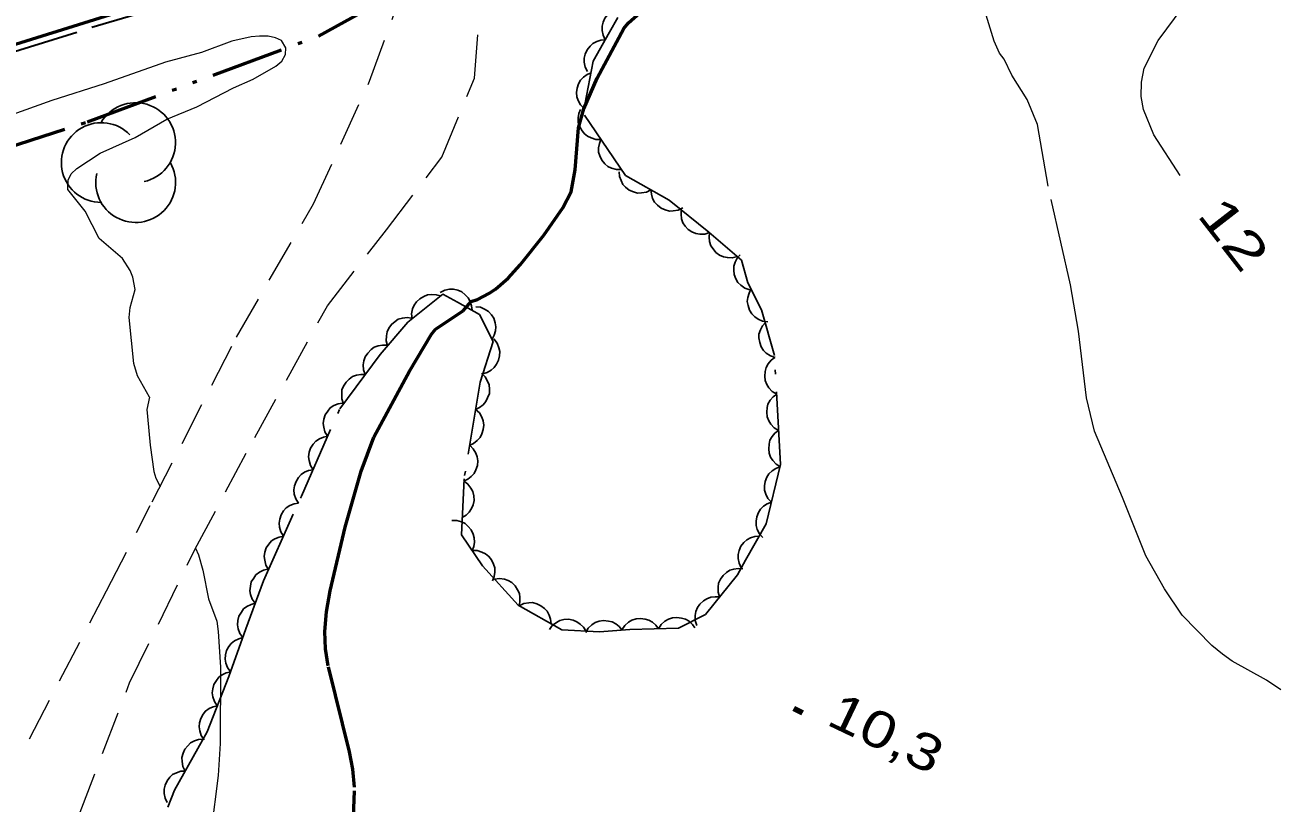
# Model space of a CAD drawing. Extents: x 355726 to 357533, y 5103782 to 5105258.
# Drawn here: x 356018.2 to 356069.6, y 5104734.5 to 5104766.6 of the extents above; entities that cross this region are included whole.
import ezdxf
from ezdxf.enums import TextEntityAlignment as Align

# ---------------------------------------------------------------- set-up
doc = ezdxf.new("R2010")
doc.units = 0
doc.header["$LTSCALE"] = 0.6
for name, pattern in [('DASH_DOUBLE_DOT', [9.2, 5, -1.2, 0.3, -1.2, 0.3, -1.2]), ('DOT_DASHED', [7.7, 5, -1.2, 0.3, -1.2]), ('LONG_DASHED', [7.5, 6, -1.5]), ('MEDIUM_DASHED', [4.5, 3, -1.5])]:
    doc.linetypes.add(name, pattern=pattern)
for name, color, linetype, lineweight in [('1', 7, 'LONG_DASHED', 53), ('19', 7, 'Continuous', 13), ('2', 7, 'LONG_DASHED', 13), ('21', 7, 'LONG_DASHED', 35), ('3', 7, 'Continuous', 140), ('4', 7, 'DASH_DOUBLE_DOT', 53), ('44', 7, 'Continuous', 25)]:
    doc.layers.add(name, color=color, linetype=linetype, lineweight=lineweight)

msp = doc.modelspace()

# ---------------------------------------------------------------- linework, layer by layer
at = {"layer": '1', "linetype": 'Continuous'}
msp.add_lwpolyline([(356036.57, 5104755.18), (356036.83, 5104755.26), (356037.3, 5104755.51), (356037.57, 5104755.69), (356038.09, 5104756.15), (356038.59, 5104756.69), (356039.56, 5104757.91), (356040.34, 5104759.04), (356040.69, 5104759.7), (356040.85, 5104760.61), (356040.99, 5104762.34), (356041.21, 5104763.12), (356041.76, 5104764.38), (356042.86, 5104766.43), (356043.05, 5104766.67), (356044.33, 5104767.8), (356044.89, 5104768.42), (356045.2, 5104768.69), (356046.34, 5104769.49), (356047.27, 5104769.98), (356048.57, 5104770.51), (356050.95, 5104771.79), (356053.92, 5104773.05)], dxfattribs=at)
at = {"layer": '1'}
for points in [[(356030.77, 5104743.26), (356031.38, 5104745.88), (356032.04, 5104748.19), (356032.57, 5104749.59), (356034.03, 5104752.32), (356034.94, 5104753.84), (356035.1, 5104754.04), (356036.24, 5104754.8), (356036.57, 5104755.18)], [(356043.49, 5104709.57), (356042.09, 5104710.94), (356037.19, 5104715.19), (356036.61, 5104715.88), (356034.23, 5104719.58), (356032.63, 5104722.18), (356031.96, 5104723.38), (356031.72, 5104724.01), (356031.58, 5104724.66), (356031.55, 5104725.34), (356031.71, 5104729.23), (356031.63, 5104731.43), (356031.77, 5104735.18), (356031.7, 5104735.91), (356031.56, 5104736.63), (356030.69, 5104740.17), (356030.57, 5104740.87), (356030.55, 5104741.59), (356030.61, 5104742.4), (356030.77, 5104743.26)]]:
    msp.add_lwpolyline(points, dxfattribs=at)
at = {"layer": '19', "linetype": 'MEDIUM_DASHED'}
for points in [[(356023.44, 5104746.93), (356026.91, 5104753.72), (356030.08, 5104759.21), (356032.39, 5104764.26), (356033.38, 5104766.97), (356033.05, 5104768.45), (356032.86, 5104769.13), (356032.09, 5104769.82)], [(355997.8, 5104670.73), (355999.08, 5104674.22), (356000.32, 5104676.94), (356001.43, 5104679.09), (356002.21, 5104680.3), (356006.1, 5104687.7), (356008.11, 5104691.5), (356009.62, 5104696.76), (356011.14, 5104701.84), (356012.62, 5104707.21), (356014.22, 5104712.09), (356015.74, 5104717.23), (356017.57, 5104723.26), (356018.4, 5104728.58), (356020.43, 5104734.04), (356022.51, 5104739.47), (356025.19, 5104744.96), (356027.66, 5104749.58), (356030.65, 5104755.01), (356033.08, 5104758.13), (356035.37, 5104761.13), (356036.71, 5104764.38), (356036.94, 5104767.51)], [(356018.38, 5104737.16), (356021.56, 5104743.26), (356023.36, 5104746.78)]]:
    msp.add_lwpolyline(points, dxfattribs=at)
at = {"layer": '2'}
for points in [[(356069.9, 5104739.18), (356069.32, 5104739.58), (356067.9, 5104740.36), (356067.5, 5104740.65), (356067.06, 5104741.01), (356065.84, 5104742.26), (356065.12, 5104743.34), (356064.35, 5104744.7), (356063.39, 5104747.11), (356062.23, 5104749.84), (356061.91, 5104751.21), (356061.58, 5104753.96), (356061.24, 5104755.87), (356060.32, 5104759.93), (356059.89, 5104762.48), (356059.46, 5104763.51), (356058.83, 5104764.51), (356058.52, 5104765.17), (356058.32, 5104765.41), (356058.1, 5104765.91), (356057.55, 5104767.73)], [(356065.76, 5104760.37), (356064.68, 5104762.05), (356064.25, 5104763.09), (356064.16, 5104763.63), (356064.17, 5104764.22), (356064.28, 5104764.79), (356064.85, 5104765.93), (356065.89, 5104767.32)], [(356023.33, 5104751.24), (356023.22, 5104750.74), (356023.24, 5104750.44), (356023.36, 5104749.26), (356023.51, 5104748.18), (356023.59, 5104747.9), (356023.76, 5104747.56)], [(356025.22, 5104745.02), (356025.35, 5104744.75), (356025.53, 5104744.11), (356025.75, 5104742.94), (356026.1, 5104742.01), (356026.16, 5104741.59), (356026.25, 5104740.12), (356026.24, 5104736.97), (356026.16, 5104735.66), (356025.8, 5104732.91)]]:
    msp.add_lwpolyline(points, dxfattribs=at)
at = {"layer": '2', "linetype": 'Continuous'}
msp.add_lwpolyline([(356023.33, 5104751.24), (356022.83, 5104752.12), (356022.68, 5104752.63), (356022.49, 5104754.53), (356022.53, 5104754.94), (356022.74, 5104755.68), (356022.64, 5104756.18), (356022.53, 5104756.46), (356022.22, 5104756.95), (356021.26, 5104757.78), (356020.68, 5104758.9), (356019.96, 5104759.8), (356019.98, 5104760.18), (356020.1, 5104760.44), (356020.33, 5104760.66), (356021.29, 5104761.3), (356022.74, 5104761.94), (356024.04, 5104762.69), (356025.28, 5104763.21), (356026.78, 5104763.98), (356027.6, 5104764.34), (356028.53, 5104764.88), (356028.77, 5104765.09), (356028.92, 5104765.36), (356028.94, 5104765.63), (356028.76, 5104765.93), (356028.51, 5104766.05), (356028.21, 5104766.12), (356027.86, 5104766.12), (356027.51, 5104766.09), (356026.72, 5104765.91), (356025.47, 5104765.44), (356023.98, 5104765.04), (356021.46, 5104764.15), (356019.3, 5104763.47), (356016.23, 5104762.36)], dxfattribs=at)
at = {"layer": '21', "linetype": 'Continuous', "lineweight": 53}
msp.add_lwpolyline([(356031.16, 5104769.57), (356022.16, 5104767.13), (356004.71, 5104761.68), (355990.39, 5104758.11), (355976.24, 5104753.88), (355961.38, 5104749.66)], dxfattribs=at)
at = {"layer": '21'}
msp.add_lwpolyline([(356002.9, 5104759.34), (356004.54, 5104760.73), (356007.99, 5104762.24), (356012.6, 5104763.88), (356020.96, 5104766.48), (356032.1, 5104769.8)], dxfattribs=at)
at = {"layer": '3'}
msp.add_line((356049.85, 5104738.41), (356050.21, 5104738.24), dxfattribs=at)
at = {"layer": '4'}
msp.add_lwpolyline([(355997.31, 5104755.28), (356004.08, 5104756.23), (356006.82, 5104757.38), (356011.73, 5104759.66), (356020.78, 5104762.59), (356030.28, 5104766.12), (356032.42, 5104767.29)], dxfattribs=at)
at = {"layer": '44', "linetype": 'DOT_DASHED'}
for points in [[(356044.72, 5104759.36), (356042.92, 5104760.38), (356041.18, 5104762.94), (356041.6, 5104765.08), (356042.27, 5104766.28), (356042.61, 5104766.88)], [(356022.38, 5104730.06), (356024.35, 5104735.05), (356025.7, 5104737.45), (356026.59, 5104739.73), (356027.3, 5104741.7), (356028.02, 5104743.68), (356029.58, 5104747.16), (356031.16, 5104750.76), (356032.82, 5104753), (356033.96, 5104754.33), (356035.41, 5104755.49), (356036.01, 5104755.16), (356036.92, 5104754.65), (356037.48, 5104753.54), (356036.94, 5104751.86), (356036.28, 5104747.88), (356036.17, 5104745.57), (356037.04, 5104744.29), (356038.5, 5104742.67), (356040.31, 5104741.65), (356041.85, 5104741.58), (356043.1, 5104741.67), (356045.11, 5104741.72), (356046.22, 5104742.29), (356047.54, 5104743.92), (356047.87, 5104744.52), (356048.72, 5104746.03), (356049.3, 5104748.47), (356049.06, 5104752.96), (356048.53, 5104754.84), (356047.96, 5104755.95), (356047.7, 5104756.89), (356046.36, 5104758.04), (356044.72, 5104759.36)]]:
    msp.add_lwpolyline(points, dxfattribs=at)
at = {"layer": '44'}
for points in [[(356042.09, 5104765.97), (356042, 5104766.15), (356041.97, 5104766.35), (356041.96, 5104766.52), (356042.01, 5104766.69), (356042.08, 5104766.86), (356042.2, 5104767.01), (356042.32, 5104767.12), (356042.48, 5104767.2), (356042.65, 5104767.26), (356042.83, 5104767.27)], [(356041.36, 5104764.66), (356041.27, 5104764.84), (356041.23, 5104765.04), (356041.23, 5104765.21), (356041.27, 5104765.38), (356041.35, 5104765.55), (356041.47, 5104765.7), (356041.58, 5104765.81), (356041.74, 5104765.89), (356041.91, 5104765.95), (356042.09, 5104765.96)], [(356041.22, 5104763.13), (356041.07, 5104763.28), (356040.97, 5104763.46), (356040.92, 5104763.61), (356040.91, 5104763.79), (356040.93, 5104763.97), (356040.99, 5104764.15), (356041.07, 5104764.3), (356041.19, 5104764.42), (356041.34, 5104764.53), (356041.51, 5104764.6)], [(356041.91, 5104761.86), (356041.71, 5104761.86), (356041.51, 5104761.92), (356041.36, 5104761.99), (356041.23, 5104762.1), (356041.11, 5104762.25), (356041.03, 5104762.42), (356040.98, 5104762.57), (356040.98, 5104762.75), (356041, 5104762.93), (356041.07, 5104763.1)], [(356042.76, 5104760.62), (356042.55, 5104760.62), (356042.35, 5104760.68), (356042.2, 5104760.75), (356042.07, 5104760.86), (356041.95, 5104761), (356041.87, 5104761.18), (356041.82, 5104761.33), (356041.82, 5104761.51), (356041.85, 5104761.69), (356041.91, 5104761.86)], [(356043.97, 5104759.78), (356043.79, 5104759.69), (356043.59, 5104759.66), (356043.42, 5104759.65), (356043.25, 5104759.7), (356043.08, 5104759.77), (356042.93, 5104759.89), (356042.82, 5104760.01), (356042.74, 5104760.17), (356042.68, 5104760.34), (356042.67, 5104760.52)], [(356045.28, 5104759.04), (356045.09, 5104758.95), (356044.89, 5104758.92), (356044.73, 5104758.91), (356044.56, 5104758.96), (356044.39, 5104759.03), (356044.24, 5104759.15), (356044.12, 5104759.27), (356044.04, 5104759.43), (356043.99, 5104759.6), (356043.97, 5104759.78)], [(356046.39, 5104758.02), (356046.19, 5104757.96), (356045.99, 5104757.96), (356045.82, 5104757.98), (356045.66, 5104758.05), (356045.51, 5104758.15), (356045.38, 5104758.29), (356045.29, 5104758.43), (356045.23, 5104758.59), (356045.21, 5104758.78), (356045.22, 5104758.96)], [(356047.53, 5104757.04), (356047.32, 5104756.98), (356047.12, 5104756.99), (356046.96, 5104757.02), (356046.8, 5104757.09), (356046.65, 5104757.2), (356046.53, 5104757.35), (356046.44, 5104757.48), (356046.39, 5104757.65), (356046.37, 5104757.84), (356046.39, 5104758.02)], [(356048.04, 5104755.67), (356047.84, 5104755.73), (356047.68, 5104755.85), (356047.55, 5104755.96), (356047.47, 5104756.12), (356047.4, 5104756.29), (356047.38, 5104756.48), (356047.38, 5104756.64), (356047.44, 5104756.81), (356047.52, 5104756.97), (356047.64, 5104757.11)], [(356035.29, 5104755.55), (356035.48, 5104755.65), (356035.68, 5104755.69), (356035.84, 5104755.69), (356036.02, 5104755.65), (356036.18, 5104755.58), (356036.33, 5104755.46), (356036.45, 5104755.34), (356036.53, 5104755.19), (356036.59, 5104755.01), (356036.61, 5104754.83)], [(356048.78, 5104754.35), (356048.57, 5104754.38), (356048.39, 5104754.46), (356048.25, 5104754.55), (356048.13, 5104754.68), (356048.03, 5104754.83), (356047.97, 5104755.02), (356047.94, 5104755.18), (356047.96, 5104755.35), (356048.01, 5104755.53), (356048.09, 5104755.69)], [(356034.14, 5104754.47), (356034.12, 5104754.68), (356034.16, 5104754.88), (356034.22, 5104755.03), (356034.32, 5104755.17), (356034.46, 5104755.3), (356034.62, 5104755.39), (356034.77, 5104755.46), (356034.95, 5104755.47), (356035.13, 5104755.46), (356035.31, 5104755.41)], [(356036.76, 5104754.97), (356036.96, 5104754.95), (356037.15, 5104754.86), (356037.29, 5104754.77), (356037.41, 5104754.64), (356037.5, 5104754.49), (356037.56, 5104754.3), (356037.59, 5104754.14), (356037.57, 5104753.97), (356037.52, 5104753.79), (356037.43, 5104753.63)], [(356033.13, 5104753.36), (356033.07, 5104753.56), (356033.08, 5104753.77), (356033.11, 5104753.93), (356033.18, 5104754.09), (356033.29, 5104754.24), (356033.44, 5104754.36), (356033.57, 5104754.45), (356033.74, 5104754.5), (356033.93, 5104754.52), (356034.11, 5104754.5)], [(356049.09, 5104752.87), (356048.89, 5104752.94), (356048.72, 5104753.05), (356048.6, 5104753.16), (356048.51, 5104753.32), (356048.45, 5104753.49), (356048.42, 5104753.68), (356048.42, 5104753.84), (356048.48, 5104754.01), (356048.56, 5104754.18), (356048.68, 5104754.31)], [(356037.51, 5104753.64), (356037.64, 5104753.47), (356037.71, 5104753.28), (356037.75, 5104753.12), (356037.74, 5104752.95), (356037.7, 5104752.77), (356037.61, 5104752.6), (356037.52, 5104752.46), (356037.39, 5104752.35), (356037.23, 5104752.26), (356037.05, 5104752.21)], [(356032.21, 5104752.18), (356032.14, 5104752.37), (356032.13, 5104752.58), (356032.15, 5104752.74), (356032.21, 5104752.91), (356032.31, 5104753.06), (356032.45, 5104753.2), (356032.58, 5104753.3), (356032.74, 5104753.36), (356032.92, 5104753.39), (356033.1, 5104753.38)], [(356049.15, 5104751.37), (356048.97, 5104751.48), (356048.83, 5104751.63), (356048.74, 5104751.76), (356048.68, 5104751.93), (356048.66, 5104752.11), (356048.68, 5104752.3), (356048.71, 5104752.46), (356048.8, 5104752.61), (356048.92, 5104752.76), (356049.07, 5104752.87)], [(356031.32, 5104750.97), (356031.25, 5104751.17), (356031.24, 5104751.37), (356031.25, 5104751.54), (356031.32, 5104751.7), (356031.42, 5104751.86), (356031.55, 5104751.99), (356031.68, 5104752.09), (356031.85, 5104752.15), (356032.03, 5104752.18), (356032.21, 5104752.18)], [(356037, 5104752.22), (356037.15, 5104752.08), (356037.25, 5104751.9), (356037.31, 5104751.75), (356037.33, 5104751.57), (356037.32, 5104751.39), (356037.25, 5104751.21), (356037.18, 5104751.06), (356037.06, 5104750.93), (356036.92, 5104750.82), (356036.75, 5104750.74)], [(356049.23, 5104749.87), (356049.05, 5104749.98), (356048.91, 5104750.13), (356048.82, 5104750.27), (356048.76, 5104750.43), (356048.74, 5104750.62), (356048.76, 5104750.81), (356048.79, 5104750.96), (356048.88, 5104751.12), (356049, 5104751.26), (356049.15, 5104751.37)], [(356030.66, 5104749.63), (356030.55, 5104749.81), (356030.5, 5104750), (356030.48, 5104750.16), (356030.5, 5104750.34), (356030.56, 5104750.51), (356030.67, 5104750.67), (356030.77, 5104750.8), (356030.92, 5104750.9), (356031.09, 5104750.97), (356031.27, 5104751)], [(356036.75, 5104750.74), (356036.91, 5104750.6), (356037.01, 5104750.42), (356037.07, 5104750.27), (356037.09, 5104750.09), (356037.07, 5104749.91), (356037.01, 5104749.73), (356036.94, 5104749.58), (356036.82, 5104749.45), (356036.67, 5104749.34), (356036.51, 5104749.26)], [(356049.31, 5104748.37), (356049.13, 5104748.48), (356048.99, 5104748.63), (356048.9, 5104748.77), (356048.84, 5104748.93), (356048.82, 5104749.12), (356048.84, 5104749.31), (356048.87, 5104749.47), (356048.96, 5104749.62), (356049.08, 5104749.76), (356049.23, 5104749.87)], [(356030.06, 5104748.25), (356029.95, 5104748.43), (356029.9, 5104748.63), (356029.87, 5104748.79), (356029.9, 5104748.97), (356029.96, 5104749.14), (356030.06, 5104749.3), (356030.17, 5104749.43), (356030.32, 5104749.52), (356030.49, 5104749.6), (356030.66, 5104749.63)], [(356036.51, 5104749.26), (356036.66, 5104749.12), (356036.76, 5104748.94), (356036.82, 5104748.79), (356036.84, 5104748.62), (356036.83, 5104748.43), (356036.76, 5104748.25), (356036.69, 5104748.1), (356036.57, 5104747.97), (356036.43, 5104747.86), (356036.26, 5104747.78)], [(356048.93, 5104746.92), (356048.79, 5104747.07), (356048.7, 5104747.25), (356048.65, 5104747.41), (356048.65, 5104747.59), (356048.67, 5104747.77), (356048.75, 5104747.94), (356048.83, 5104748.09), (356048.96, 5104748.21), (356049.11, 5104748.31), (356049.28, 5104748.37)], [(356029.46, 5104746.88), (356029.35, 5104747.06), (356029.29, 5104747.25), (356029.27, 5104747.42), (356029.3, 5104747.59), (356029.36, 5104747.77), (356029.46, 5104747.93), (356029.57, 5104748.05), (356029.71, 5104748.15), (356029.88, 5104748.22), (356030.06, 5104748.25)], [(356036.28, 5104747.78), (356036.44, 5104747.66), (356036.56, 5104747.49), (356036.64, 5104747.35), (356036.68, 5104747.18), (356036.69, 5104746.99), (356036.65, 5104746.81), (356036.59, 5104746.65), (356036.49, 5104746.51), (356036.36, 5104746.38), (356036.2, 5104746.28)], [(356028.84, 5104745.51), (356028.73, 5104745.69), (356028.68, 5104745.89), (356028.66, 5104746.05), (356028.69, 5104746.22), (356028.75, 5104746.4), (356028.85, 5104746.56), (356028.96, 5104746.68), (356029.11, 5104746.78), (356029.28, 5104746.85), (356029.46, 5104746.88)], [(356048.58, 5104745.46), (356048.44, 5104745.61), (356048.35, 5104745.79), (356048.3, 5104745.95), (356048.3, 5104746.13), (356048.33, 5104746.31), (356048.4, 5104746.49), (356048.48, 5104746.63), (356048.61, 5104746.75), (356048.76, 5104746.85), (356048.93, 5104746.92)], [(356035.77, 5104746.16), (356035.98, 5104746.16), (356036.17, 5104746.1), (356036.32, 5104746.04), (356036.45, 5104745.92), (356036.57, 5104745.78), (356036.65, 5104745.6), (356036.7, 5104745.45), (356036.71, 5104745.27), (356036.68, 5104745.09), (356036.61, 5104744.92)], [(356028.23, 5104744.14), (356028.12, 5104744.32), (356028.07, 5104744.52), (356028.05, 5104744.68), (356028.07, 5104744.86), (356028.13, 5104745.03), (356028.24, 5104745.19), (356028.35, 5104745.32), (356028.49, 5104745.41), (356028.66, 5104745.48), (356028.84, 5104745.51)], [(356047.69, 5104744.21), (356047.6, 5104744.4), (356047.57, 5104744.6), (356047.56, 5104744.76), (356047.61, 5104744.93), (356047.68, 5104745.1), (356047.8, 5104745.25), (356047.92, 5104745.36), (356048.07, 5104745.44), (356048.25, 5104745.5), (356048.43, 5104745.52)], [(356036.61, 5104744.92), (356036.82, 5104744.92), (356037.01, 5104744.86), (356037.16, 5104744.79), (356037.3, 5104744.68), (356037.41, 5104744.54), (356037.49, 5104744.36), (356037.55, 5104744.21), (356037.55, 5104744.03), (356037.52, 5104743.85), (356037.45, 5104743.68)], [(356046.8, 5104743.01), (356046.74, 5104743.21), (356046.74, 5104743.41), (356046.76, 5104743.58), (356046.84, 5104743.74), (356046.94, 5104743.89), (356047.08, 5104744.02), (356047.22, 5104744.11), (356047.38, 5104744.16), (356047.57, 5104744.19), (356047.75, 5104744.17)], [(356027.68, 5104742.75), (356027.56, 5104742.92), (356027.49, 5104743.11), (356027.46, 5104743.27), (356027.48, 5104743.45), (356027.52, 5104743.63), (356027.62, 5104743.79), (356027.71, 5104743.92), (356027.85, 5104744.03), (356028.02, 5104744.11), (356028.19, 5104744.16)], [(356037.53, 5104743.74), (356037.74, 5104743.77), (356037.94, 5104743.74), (356038.1, 5104743.69), (356038.25, 5104743.6), (356038.38, 5104743.47), (356038.48, 5104743.31), (356038.56, 5104743.16), (356038.58, 5104742.99), (356038.58, 5104742.8), (356038.54, 5104742.63)], [(356027.17, 5104741.34), (356027.05, 5104741.51), (356026.98, 5104741.7), (356026.95, 5104741.86), (356026.96, 5104742.04), (356027.01, 5104742.22), (356027.11, 5104742.38), (356027.2, 5104742.52), (356027.34, 5104742.62), (356027.51, 5104742.7), (356027.68, 5104742.75)], [(356038.55, 5104742.64), (356038.74, 5104742.74), (356038.94, 5104742.77), (356039.1, 5104742.78), (356039.27, 5104742.73), (356039.44, 5104742.65), (356039.59, 5104742.53), (356039.7, 5104742.42), (356039.78, 5104742.26), (356039.84, 5104742.09), (356039.86, 5104741.91)], [(356045.86, 5104741.84), (356045.8, 5104742.04), (356045.8, 5104742.25), (356045.82, 5104742.41), (356045.89, 5104742.57), (356045.99, 5104742.72), (356046.14, 5104742.85), (356046.27, 5104742.94), (356046.44, 5104743), (356046.62, 5104743.02), (356046.8, 5104743.01)], [(356042.78, 5104741.66), (356042.9, 5104741.84), (356043.05, 5104741.97), (356043.19, 5104742.06), (356043.36, 5104742.11), (356043.54, 5104742.13), (356043.73, 5104742.1), (356043.89, 5104742.06), (356044.04, 5104741.97), (356044.18, 5104741.85), (356044.28, 5104741.7)], [(356044.28, 5104741.7), (356044.4, 5104741.88), (356044.55, 5104742.01), (356044.69, 5104742.1), (356044.86, 5104742.15), (356045.04, 5104742.17), (356045.23, 5104742.14), (356045.39, 5104742.1), (356045.54, 5104742.01), (356045.68, 5104741.88), (356045.78, 5104741.74)], [(356039.79, 5104741.67), (356039.91, 5104741.84), (356040.08, 5104741.96), (356040.22, 5104742.04), (356040.39, 5104742.08), (356040.58, 5104742.09), (356040.77, 5104742.05), (356040.92, 5104741.99), (356041.06, 5104741.89), (356041.19, 5104741.76), (356041.29, 5104741.61)], [(356041.29, 5104741.54), (356041.39, 5104741.72), (356041.54, 5104741.86), (356041.68, 5104741.96), (356041.84, 5104742.01), (356042.02, 5104742.04), (356042.22, 5104742.02), (356042.37, 5104741.99), (356042.53, 5104741.9), (356042.67, 5104741.79), (356042.78, 5104741.65)], [(356026.66, 5104739.93), (356026.54, 5104740.1), (356026.47, 5104740.29), (356026.44, 5104740.45), (356026.45, 5104740.63), (356026.5, 5104740.8), (356026.6, 5104740.97), (356026.69, 5104741.1), (356026.83, 5104741.21), (356027, 5104741.29), (356027.17, 5104741.34)], [(356026.12, 5104738.53), (356026, 5104738.7), (356025.94, 5104738.89), (356025.91, 5104739.06), (356025.93, 5104739.23), (356025.98, 5104739.41), (356026.08, 5104739.57), (356026.18, 5104739.7), (356026.32, 5104739.8), (356026.49, 5104739.89), (356026.67, 5104739.93)], [(356025.58, 5104737.13), (356025.46, 5104737.3), (356025.4, 5104737.5), (356025.37, 5104737.66), (356025.39, 5104737.83), (356025.44, 5104738.01), (356025.54, 5104738.18), (356025.63, 5104738.31), (356025.78, 5104738.41), (356025.95, 5104738.49), (356026.12, 5104738.53)], [(356024.8, 5104735.84), (356024.7, 5104736.03), (356024.67, 5104736.23), (356024.66, 5104736.4), (356024.71, 5104736.57), (356024.78, 5104736.74), (356024.9, 5104736.88), (356025.02, 5104737), (356025.18, 5104737.08), (356025.35, 5104737.14), (356025.53, 5104737.15)], [(356024.06, 5104734.54), (356023.97, 5104734.72), (356023.93, 5104734.92), (356023.93, 5104735.09), (356023.97, 5104735.26), (356024.05, 5104735.43), (356024.17, 5104735.58), (356024.28, 5104735.69), (356024.44, 5104735.77), (356024.62, 5104735.83), (356024.8, 5104735.84)]]:
    msp.add_lwpolyline(points, dxfattribs=at)
for centre, start, end in [((356022.757, 5104761.729), 282.2692, 149.7263), ((356021.343, 5104760.907), 44.1154, 269.804), ((356022.757, 5104760.085), 166.9369, 29.6212)]:
    msp.add_arc(centre, 1.644, start, end, dxfattribs=at)

# ---------------------------------------------------------------- texts
at = {"layer": '2', "width": 1.4}
msp.add_text('12', height=1.5, rotation=307.846, dxfattribs=at).set_placement((356067.376, 5104757.51), align=Align.CENTER)
at = {"layer": '3', "width": 1.25}
msp.add_text('10,3   ', height=1.5, rotation=334.423, dxfattribs=at).set_placement((356051.14, 5104737.78))

doc.saveas('drawing.dxf')
